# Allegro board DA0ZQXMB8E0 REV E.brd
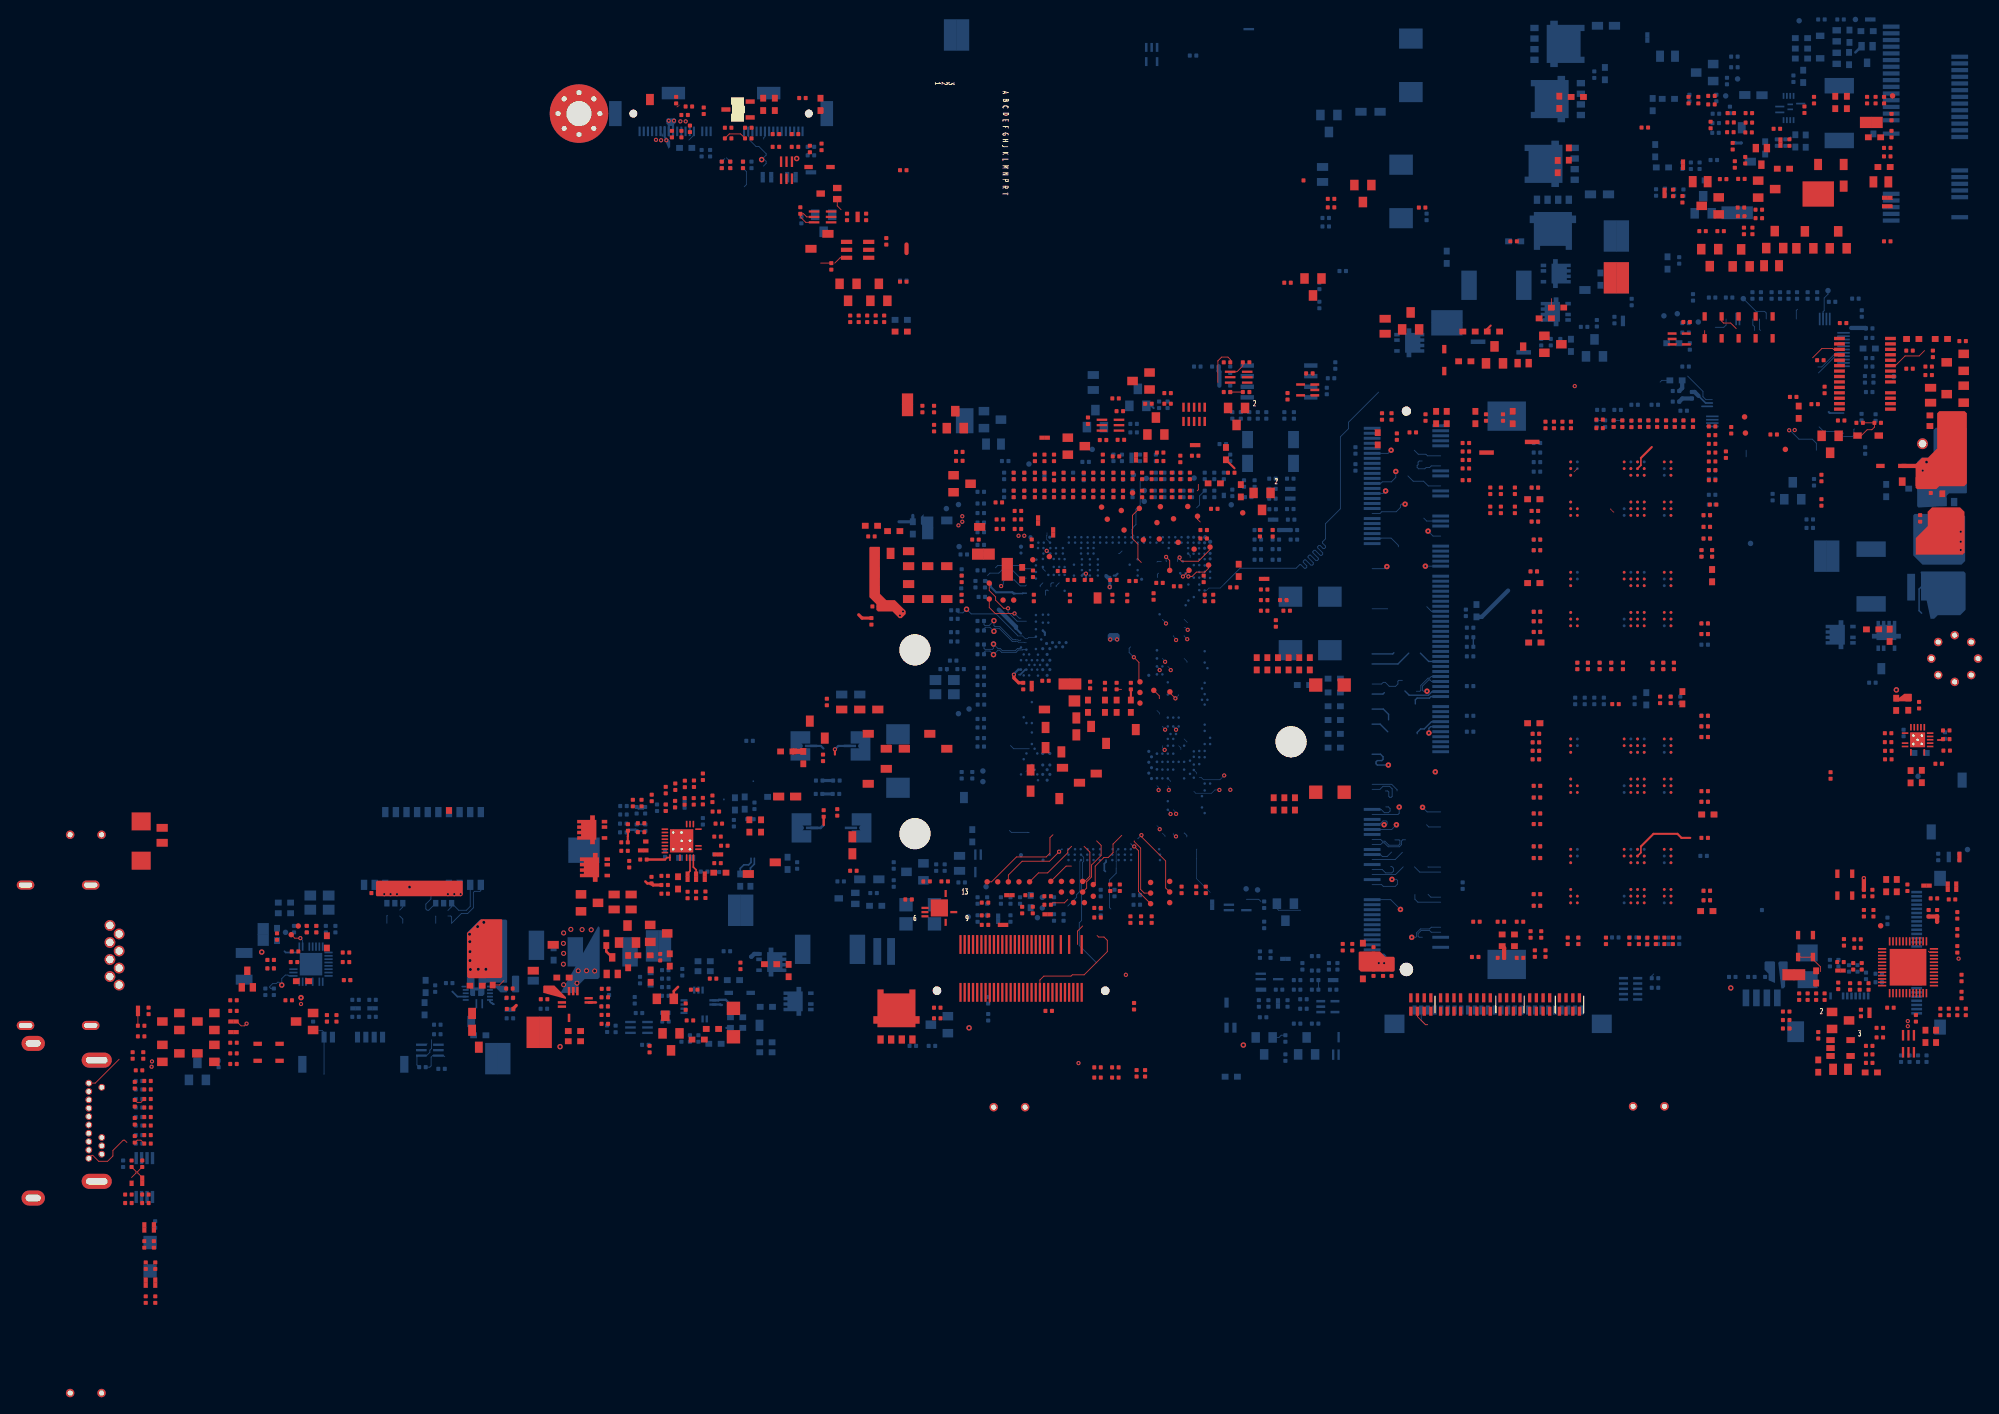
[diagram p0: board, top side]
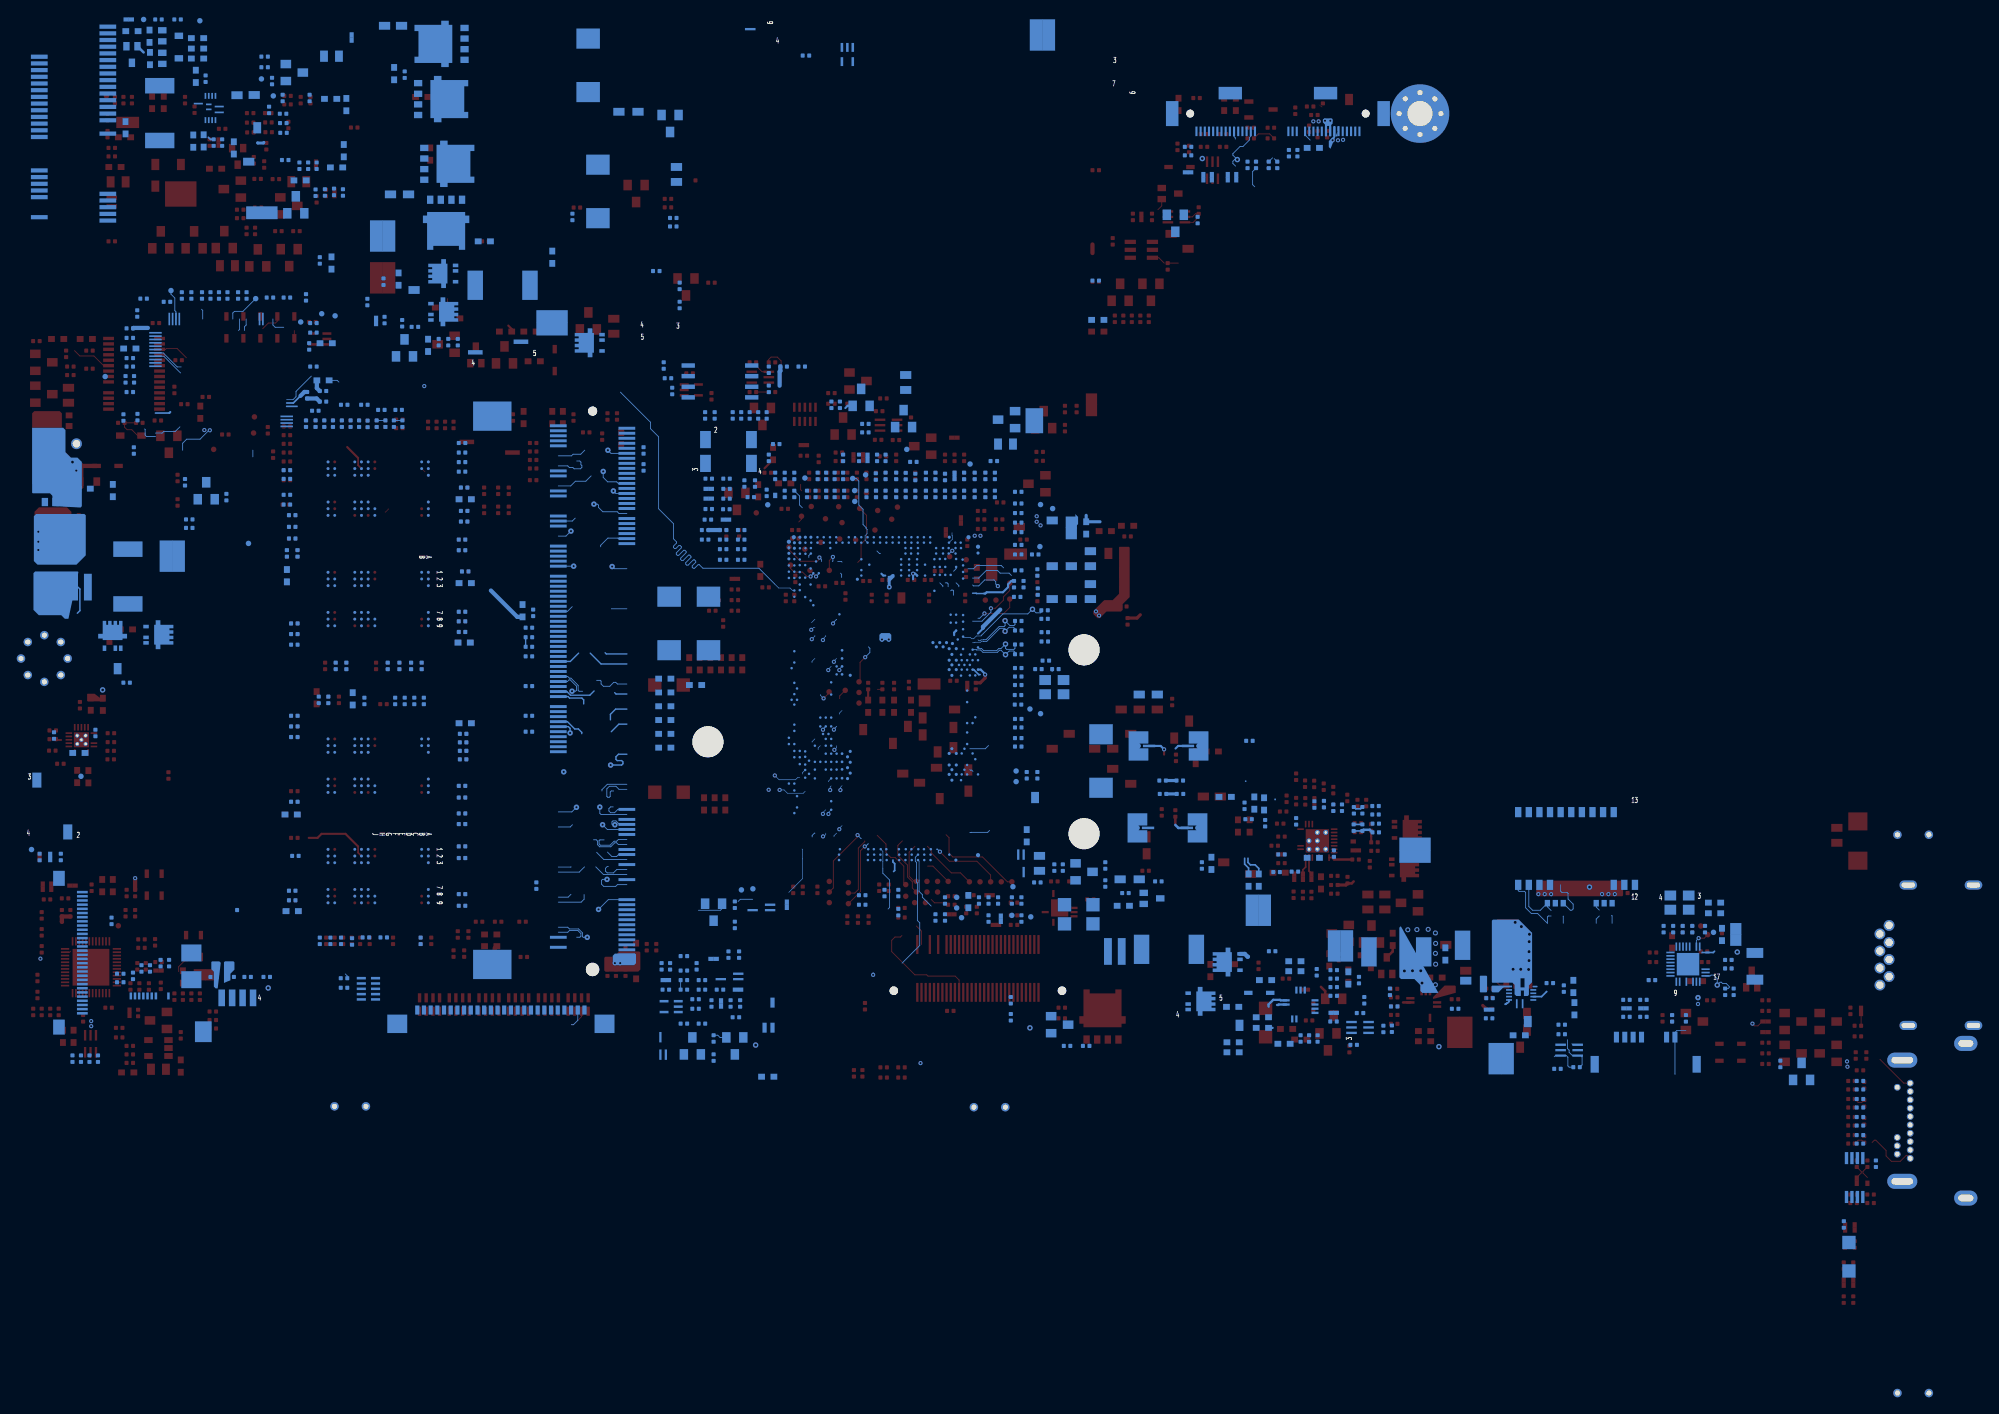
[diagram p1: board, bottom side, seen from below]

No outline. copper layers: TOP, SGND, IN1, IN2, SVCC, IN3, SGND1, BOTTOM. Coordinates in mm from the lowest, leftmost part position.

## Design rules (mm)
constraint set DEFAULT: min track width 0.102
net group W15-TB: nets SM_RCOMP_2

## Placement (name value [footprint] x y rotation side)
BT6  -  [ML1220-SMT]  214.22 66.2 295 bottom
C6  -  [CC0805]  75.61 152.88 0 top
C7  -  [CC0402]  77.84 152.81 90 top
C8  -  [CC0402#2]  219.19 152.81 90 top
C9  -  [CC0603#2]  88.26 152.3 270 top
C10  -  [CC0402]  79.37 152.05 0 top
C11  -  [CC0402]  79.49 149.38 270 top
C12  -  [CC0402]  81.14 151.54 90 top
C13  -  [CC0402]  78.86 151.03 0 top
C14  -  [CC0402#2]  105.02 151.03 0 top
C15  -  [CC0402]  223.26 150.78 90 top
C16  -  [CC0402]  86.48 149.51 0 top
C17  -  [CC0402]  77.33 148.74 270 top
C18  -  [CC0402]  78.48 148.74 90 top
C19  -  [CC0402]  223.26 148.74 270 top
C20  -  [CC0603#2]  221.23 148.36 0 top
C21  -  [CC0402]  86.48 148.24 0 top
C22  -  [CC0402#2]  139.18 147.09 90 top
C23  -  [CC0402]  222.75 147.09 0 top
C24  -  [CC0402#2]  144.39 146.71 180 top
C25  -  [CC0402#2]  146.42 146.71 180 top
C26  -  [CC0402#2]  147.95 146.71 270 top
C27  -  [CC0402#2]  105.02 146.46 180 top
C28  -  [CC0402]  222.75 146.08 0 top
C29  -  [CC0402#2]  135.12 145.57 90 top
C30  -  [CC0402#2]  105.02 145.44 180 top
C31  -  [CC0402]  83.3 145.06 270 top
C32  -  [CC0402]  84.32 145.06 270 top
C33  -  [CC0402]  85.84 145.06 90 top
C34  -  [CC0402#2]  133.6 145.06 0 top
C35  -  [CC0603]  137.15 145.06 0 top
C36  -  [CC0603]  139.82 145.01 180 top
C37  -  [CC0603]  142.49 145.06 0 top
C38  -  [CC0603]  145.28 145.06 0 top
C39  -  [CC0603]  148.07 145.06 180 top
C40  -  [CC0603#2]  222.37 144.81 0 top
C41  -  [CC0402#2]  105.02 143.41 180 top
C42  -  [CC0603]  137.41 143.03 270 top
C43  -  [CC0603]  138.93 143.03 270 top
C44  -  [CC0603]  140.4 143.03 90 top
C45  -  [CC0603]  142.1 143.03 90 top
C46  -  [CC0603]  144.39 143.03 270 top
C47  -  [CC0603]  145.91 143.03 90 top
C48  -  [CC0603]  135.12 142.47 0 top
C49  -  [CC0603]  150.61 142.52 270 top
C50  -  [CC0402#2]  105.02 142.39 180 top
C51  -  [CC0402#2]  148.71 142.14 180 top
C52  -  [CC0402#2]  130.67 141.96 0 top
C53  -  [CC0402#2]  105.02 141.38 180 top
C54  -  [CC0603]  135.12 141.12 0 top
C55  -  [CC0402#2]  145.79 140.49 90 top
C56  -  [CC0402#2]  148.07 140.49 270 top
C57  -  [CC0402#2]  149.22 140.49 270 top
C58  -  [CC0603]  137.41 140.36 270 top
C59  -  [CC0603]  138.93 140.36 270 top
C60  -  [CC0603]  140.4 140.36 270 top
C61  -  [CC0603]  142.1 140.36 270 top
C62  -  [CC0603]  144.39 140.36 270 top
C63  -  [CC0603]  104.77 140.11 0 top
C64  -  [CC0402#2]  135.37 139.85 0 top
C65  -  [CC0603]  150.61 139.73 270 top
C66  -  [CC0603]  152.14 139.73 270 top
C67  -  [CC0402#2]  148.58 138.84 0 top
C68  -  [CC0402#2]  105.02 138.71 180 top
C69  -  [CC0603]  135.12 138.58 180 top
C70  -  [CC0402#2]  145.79 138.46 90 top
C71  -  [CC0402#2]  105.02 137.7 180 top
C72  -  [CC0603]  137.41 137.7 90 top
C73  -  [CC0603]  138.93 137.7 90 top
C74  -  [CC0603]  140.4 137.7 270 top
C75  -  [CC0603]  142.1 137.7 270 top
C76  -  [CC0603]  144.39 137.7 90 top
C77  -  [CC0805#2]  148.3 137.19 0 top
C78  -  [CC0402#2]  105.02 136.68 0 top
C79  -  [CC0402#2]  145.79 136.43 90 top
C80  -  [CC0805]  93.97 135.92 90 top
C81  -  [CC0805]  96 135.92 270 top
C82  -  [CC0402]  102.99 135.92 270 top
C83  -  [CC0603]  134.99 135.92 0 top
C84  -  [CC0402]  222.75 135.92 180 top
C85  -  [CC0402#2]  139.56 134.77 270 top
C86  -  [CC0402#2]  140.58 134.77 90 top
C87  -  [CC0402#2]  105.02 134.52 0 top
C88  -  [CC0603]  137.02 134.52 90 top
C89  -  [CC0603]  138.29 134.52 270 top
C90  -  [CC0603]  141.85 134.52 270 top
C91  -  [CC0603]  143.37 134.52 90 top
C92  -  [CC0402#2]  144.77 134.52 90 top
C93  -  [RC0603#2]  134.99 134.39 0 top
C94  -  [CC0603]  147.06 134.39 270 top
C95  -  [CC0603]  149.09 134.39 270 top
C96  -  [CC0603]  150.49 134.39 270 top
C97  -  [CC0603]  130.29 132.74 90 top
C98  -  [CC0603]  131.69 131.85 90 top
C99  -  [CC0603]  134.23 131.85 90 top
C100  -  [CC0603]  135.88 131.85 270 top
C101  -  [CC0603]  139.95 131.85 90 top
C102  -  [CC0402#2]  132.96 130.71 90 top
C103  -  [CC0603]  128.52 130.58 90 top
C104  -  [CC0402#2]  130.04 130.33 270 top
C105  -  [CC0402#2]  138.29 129.82 90 top
C106  -  [CC0402#2]  128.52 128.04 90 top
C107  -  [CC0603]  129.91 127.79 90 top
C108  -  [CC0402#2]  105.03 127.79 0 top
C109  -  [CC0603]  104.77 126.52 0 top
C110  -  [CC0402]  217.47 126.14 0 top
C111  -  [CC0603#2]  104.77 125.12 0 top
C112  -  [CC0402#2]  140.83 125 270 top
C113  -  [CC0402#2]  141.85 125 270 top
C114  -  [CC0402#2]  143.12 125 270 top
C115  -  [CC0402#2]  144.14 125 270 top
C116  -  [CC0402#2]  145.41 125 270 top
C117  -  [CC0402#2]  146.42 125 270 top
C118  -  [CC0402#2]  147.44 125 270 top
C119  -  [CC0402#2]  148.58 125 270 top
C120  -  [CC0402#2]  105.02 123.85 0 top
C121  -  [CC0402#2]  105.02 122.84 180 top
C122  -  [CC0402]  225.42 122.84 180 top
C123  -  [CC0603#2]  229.23 124.23 180 top
C124  -  [CC0402]  214.75 121.69 0 top
C125  -  [CC0402]  220.11 110.89 270 bottom
C126  -  [CC0402]  215.26 118.14 90 top
C127  -  [CC0402]  150.99 117.38 270 top
C128  -  [CC0402]  162.3 114.96 270 top
C129  -  [CC0402]  163.44 114.96 270 top
C130  -  [CC0603#2]  212.16 115.47 90 top
C131  -  [CC0402]  167.5 114.84 270 top
C132  -  [CC0603#2]  168.77 114.84 90 top
C133  -  [CC0603#2]  170.04 114.84 90 top
C134  -  [CC0603#2]  173.47 114.84 90 top
C135  -  [CC0402]  174.74 114.84 270 top
C136  -  [CC0402]  176.78 114.84 270 top
C137  -  [CC0603#2]  177.92 114.84 90 top
C138  -  [CC0402]  188.33 114.58 0 top
C139  -  [CC0402]  219.45 114.2 0 top
C140  -  [CC0402]  181.86 113.95 270 top
C141  -  [CC0402]  182.87 113.95 270 top
C142  -  [CC0402]  183.89 113.95 270 top
C143  -  [CC0402]  184.9 113.95 270 top
C144  -  [CC0402]  204.08 113.31 90 top
C145  -  [CC0402]  209.16 112.8 180 top
C146  -  [CC0402]  164.08 112.55 90 top
C147  -  [CC0603#2]  161.79 112.3 90 top
C148  -  [CC0402]  203.45 110.39 90 top
C152  -  [CC0402]  214.88 107.6 270 top
C153  -  [CC0402]  172.33 107.34 0 top
C154  -  [CC0402]  201.79 107.34 180 top
C156  -  [CC0402]  180.59 106.45 0 top
C157  -  [CC0603#2]  145.41 106.07 270 top
C158  -  [CC0603#2]  180.46 105.06 180 top
C160  -  [CC0402]  116.45 104.68 180 top
C161  -  [CC0402]  214.88 104.68 270 top
C162  -  [CC0402]  201.92 104.42 180 top
C163  -  [CC0402]  142.23 103.91 0 top
C164  -  [CC0402]  180.59 103.66 0 top
C165  -  [CC0402]  201.16 103.15 180 top
C166  -  [CC0805]  114.16 102.64 90 top
C167  -  [CC0402]  180.59 102.39 0 top
C168  -  [CC0603#2]  101.21 101.88 180 top
C169  -  [CC0402]  201.16 101.75 180 top
C170  -  [CC0402]  147.69 100.99 90 top
C171  -  [CC0402]  149.22 100.99 90 top
C172  -  [CC0402]  101.21 100.61 0 top
C173  -  [CC0402]  201.16 100.36 180 top
C174  -  [CC0402]  113.66 100.23 0 top
C175  -  [CC0402]  180.84 100.23 0 top
C176  -  [CC0402]  120.39 99.85 90 top
C177  -  [CC0402]  180.84 98.96 0 top
C178  -  [CC0402]  201.79 98.58 270 top
C179  -  [CC0805]  107.94 97.94 90 top
C180  -  [CC0805]  110.23 97.94 90 top
C181  -  [CC0603#2]  145.15 96.55 270 top
C182  -  [CC0402]  123.89 96.47 180 top
C183  -  [CC0402]  180.46 96.42 0 top
C184  -  [CC0805]  102.61 96.29 0 top
C185  -  [CC0603#2]  119.24 96.17 90 top
C186  -  [CC0402]  120.54 96.14 270 top
C187  -  [CC0603#2]  201.79 95.91 270 top
C188  -  [CC0402]  112.01 95.53 90 top
C189  -  [CC0402]  140.96 95.53 90 top
C190  -  [CC0402]  125.09 95.4 180 top
C191  -  [CC0402]  127.12 95.4 0 top
C192  -  [CC0402]  130.17 95.4 180 top
C193  -  [CC0402]  132.45 95.28 180 top
C194  -  [CC0603#2]  180.46 95.02 180 top
C195  -  [CC0402]  144.52 94.52 0 top
C196  -  [CC0805]  102.61 94.01 0 top
C197  -  [CC0805]  107.94 94.01 90 top
C198  -  [CC0805]  110.23 94.01 90 top
C199  -  [CC0402]  112.01 93.25 270 top
C200  -  [CC0402]  120.64 93.25 270 top
C201  -  [CC0402]  124.96 93.25 90 top
C202  -  [CC0805]  127.37 93.25 180 top
C203  -  [CC0402]  130.04 93.25 90 top
C204  -  [CC0402]  131.82 93.25 270 top
C205  -  [CC0402]  150.49 92.99 0 top
C206  -  [CC0402]  101.72 92.23 0 top
C207  -  [CC0402]  180.84 91.59 0 top
C208  -  [CC0402]  101.21 90.45 90 top
C209  -  [CC0402]  180.84 90.45 0 top
C210  -  [CC0402]  149.6 90.2 270 top
C211  -  [CC0402]  200.91 90.2 180 top
C212  -  [CC0402]  180.84 89.18 0 top
C213  -  [CC0402]  200.91 88.93 180 top
C214  -  [CC0603#2]  180.59 87.91 180 top
C215  -  [CC0603#2]  147.31 85.37 90 top
C216  -  [CC0603#2]  148.58 85.37 270 top
C217  -  [CC0603#2]  149.85 85.37 270 top
C218  -  [CC0603#2]  151.12 85.37 90 top
C219  -  [CC0603#2]  152.39 85.37 270 top
C220  -  [CC0603#2]  153.66 85.37 90 top
C221  -  [CC0402]  185.67 85.12 90 top
C222  -  [CC0402]  186.94 85.12 90 top
C223  -  [CC0402]  188.33 85.12 90 top
C224  -  [CC0402]  189.73 85.12 90 top
C225  -  [CC0402]  191.13 85.12 90 top
C226  -  [CC0402]  194.68 85.12 90 top
C227  -  [CC0402]  195.95 85.12 90 top
C228  -  [CC0402]  197.22 85.12 90 top
C229  -  [CC0402]  127.37 82.83 90 top
C230  -  [CC0402]  129.15 82.7 270 top
C231  -  [CC0402]  130.55 82.7 270 top
C232  -  [CC0402]  132.25 82.7 270 top
C233  -  [CC0603#2]  198.24 81.31 90 top
C234  -  [CC0402]  196.84 81.05 270 top
C235  -  [CC0805]  97.65 80.8 90 top
C236  -  [CC0805]  99.81 80.8 90 top
C237  -  [CC0805]  101.97 80.8 90 top
C238  -  [CC0805]  121.91 80.8 90 top
C239  -  [CC0402]  190.24 80.55 180 top
C240  -  [CC0603#2]  127.12 80.29 270 top
C241  -  [CC0402]  200.91 79.15 180 top
C242  -  [CC0805]  124.83 78.89 180 top
C243  -  [CC0805]  94.73 78.51 0 top
C244  -  [CC0603#2]  180.46 78.26 180 top
C245  -  [CC0805]  128.39 77.88 0 top
C246  -  [CC0402]  200.91 77.88 180 top
C247  -  [CC0805]  121.15 77.75 180 top
C248  -  [CC0805]  131.94 77.5 180 top
C249  -  [CC0402]  180.71 76.99 0 top
C250  -  [CC0805]  124.83 76.86 180 top
C251  -  [CC0402]  200.91 76.61 180 top
C252  -  [CC0805]  94.73 76.48 180 top
C253  -  [CC0805]  100.83 76.1 270 top
C254  -  [CC0805]  102.99 76.1 90 top
C255  -  [CC0805]  105.15 76.1 90 top
C256  -  [CC0805]  108.2 76.1 270 top
C257  -  [CC0805]  110.23 76.1 90 top
C258  -  [CC0402]  180.71 75.97 0 top
C259  -  [CC0805]  128.39 75.85 180 top
C260  -  [CC0805]  121.15 75.34 180 top
C261  -  [CC0402]  180.71 74.96 0 top
C262  -  [CC0805]  124.83 74.83 0 top
C263  -  [CC0402]  180.71 73.94 0 top
C264  -  [CC0805]  128.11 73.13 90 top
C265  -  [CC0805]  121.15 72.67 0 top
C266  -  [CC0805]  124.07 72.04 270 top
C267  -  [CC0805]  126.1 72.04 90 top
C268  -  [CC0805]  100.83 71.91 90 top
C269  -  [CC0805]  102.99 71.91 270 top
C270  -  [CC0402]  180.84 70.77 0 top
C271  -  [CC0805]  121.15 70.13 0 top
C272  -  [CC0402]  200.91 70.13 180 top
C273  -  [CC0402]  180.84 69.37 0 top
C274  -  [CC0805]  124.58 69.24 0 top
C275  -  [CC0402]  200.91 68.86 180 top
C276  -  [CC0603#2]  149.34 68.61 90 top
C277  -  [CC0603#2]  150.61 68.61 90 top
C278  -  [CC0603#2]  151.88 68.61 270 top
C279  -  [CC0402]  180.84 67.46 0 top
C280  -  [CC0603#2]  201.29 67.34 0 top
C281  -  [CC0402]  180.84 66.19 180 top
C282  -  [CC0805]  98.04 64.67 180 top
C283  -  [CC1808]  13.83 64.16 90 top
C284  -  [CC0402]  180.84 63.53 0 top
C285  -  [CC0805]  98.04 62.64 180 top
C286  -  [CC0402]  180.84 62.13 0 top
C287  -  [CC0402]  109.97 59.34 0 top
C288  -  [CC0603#2]  222.62 58.83 90 top
C289  -  [CC0603#2]  223.89 58.83 90 top
C290  -  [CC0402]  225.16 58.57 270 top
C291  -  [CC0402]  201.16 58.22 180 top
C292  -  [CC0402]  41.77 57.94 180 top
C293  -  [CC0402]  180.84 57.81 0 top
C294  -  [CC0402]  228.34 57.3 180 top
C295  -  [CC0402]  230.5 57.18 0 top
C296  -  [CC0402]  201.16 57.08 180 top
C297  -  [CC0402]  180.84 56.42 0 top
C298  -  [CC0603#2]  201.16 55.78 0 top
C299  -  [CC0402]  219.96 55.53 270 top
C300  -  [CC0402]  221.1 55.53 270 top
C301  -  [CC0402]  227.7 55.53 270 top
C302  -  [CC0402]  228.72 55.53 270 top
C303  -  [CC0402]  231.13 55.27 90 top
C304  -  [CC0402]  176.52 54.51 180 top
C305  -  [CC0402]  33.65 53.62 270 top
C306  -  [CC0402]  34.79 53.62 270 top
C307  -  [CC0402]  231.13 53.24 270 top
C308  -  [CC0402]  181.35 52.99 90 top
C309  -  [CC0402]  30.09 52.73 90 top
C310  -  [CC0402]  184.52 52.22 90 top
C311  -  [CC0402]  185.79 52.22 90 top
C312  -  [CC0402]  189.09 52.22 90 top
C313  -  [CC0402]  191.89 52.22 90 top
C314  -  [CC0402]  193.03 52.22 90 top
C315  -  [CC0402]  194.05 52.22 90 top
C316  -  [CC0402]  195.06 52.22 90 top
C317  -  [CC0402]  196.08 52.22 90 top
C318  -  [CC0402]  197.1 52.22 90 top
C319  -  [CC0603#2]  36.06 52.1 270 top
C320  -  [CC0402]  219.19 52.4 180 top
C321  -  [CC0402]  158.74 51.46 270 top
C322  -  [CC0402]  217.57 52.05 270 top
C323  -  [CC0402]  231.13 51.21 270 top
C324  -  [CC0402]  32.25 50.95 0 top
C325  -  [CC0402]  38.35 50.83 180 top
C326  -  [CC0402]  181.86 50.7 270 top
C327  -  [CC0402]  176.52 50.19 180 top
C328  -  [CC0402]  32.12 49.68 180 top
C329  -  [CC0402]  38.35 49.68 180 top
C330  -  [CC0402]  218.68 49.18 270 top
C331  -  [CC0402]  219.69 49.18 270 top
C332  -  [CC0603#2]  160.01 48.41 90 top
C333  -  [CC0402]  162.42 48.41 270 top
C334  -  [CC0402]  163.44 48.41 90 top
C335  -  [CC0603#2]  214.24 47.91 270 top
C336  -  [CC0402]  38.47 47.53 180 top
C337  -  [CC0603#2]  33.14 47.4 180 top
C338  -  [CC0402]  218.3 46.76 270 top
C339  -  [CC0402]  220.51 46.76 90 top
C340  -  [CC0402]  231.64 45.75 90 top
C341  -  [CC0402]  212.21 45.54 90 top
C342  -  [CC0402]  213.22 45.54 90 top
C343  -  [CC0402]  214.24 45.54 90 top
C344  -  [CC0402]  215.26 45.54 90 top
C345  -  [CC0402]  210.66 43.77 180 top
C346  -  [CC0402]  226.18 42.95 90 top
C347  -  [CC0402]  229.1 43.72 90 top
C348  -  [CC0402]  230.12 43.72 90 top
C349  -  [CC0402]  232.15 43.72 90 top
C350  -  [CC0402]  36.06 42.95 270 top
C351  -  [CC0402]  37.2 42.95 270 top
C352  -  [CC0402]  214.49 40.92 270 top
C353  -  [CC0402]  13.83 40.79 180 top
C354  -  [CC0603#2]  227.32 40.79 270 top
C355  -  [CC0603#2]  228.59 40.79 270 top
C356  -  [CC0402]  14.09 38.51 270 top
C357  -  [CC0402]  220.59 37.62 180 top
C358  -  [CC0603#2]  214.49 37.24 270 top
C359  -  [CC0402]  13.58 36.73 180 top
C360  -  [CC0603#2]  220.84 36.48 0 top
C361  -  [CC0402]  14.6 35.46 0 top
C362  -  [CC0402]  14.6 34.44 0 top
C363  -  [CC0402]  14.6 33.3 0 top
C364  -  [CC0402]  14.6 32.29 0 top
C365  -  [CC0402]  14.6 31.14 0 top
C366  -  [CC0402]  14.6 30.13 0 top
C367  -  [CC0402]  14.6 28.98 0 top
C368  -  [CC0402]  14.6 27.97 0 top
C369  -  [CC0402]  12.69 25.55 90 top
C370  -  [CC0402]  13.96 25.55 90 top
C371  -  [CC0402]  12.31 21.87 0 top
C372  -  [CC0402]  14.34 21.87 180 top
C373  -  [CC0402]  14.38 13.36 270 top
C374  -  [CC0402]  15.52 13.36 270 top
C375  -  [CC0402#2]  134.99 160.68 0 bottom
C376  -  [CC0402]  204.46 156.75 0 bottom
C377  -  [CC0402#2]  134.48 155.86 0 bottom
C378  -  [CC0402#2]  157.98 154.84 90 bottom
C379  -  [CC0603]  104.77 154.33 0 bottom
C380  -  [CC0402#2]  142.23 153.95 180 bottom
C381  -  [CC0402#2]  144.26 153.95 0 bottom
C382  -  [CC0402#2]  105.02 153.06 0 bottom
C383  -  [CC0402#2]  159 153.06 0 bottom
C384  -  [CC0402#2]  105.02 152.05 180 bottom
C385  -  [CC0402#2]  105.02 151.03 0 bottom
C386  -  [CC0402#2]  105.02 150.01 0 bottom
C387  -  [CC0402#2]  105.02 149 0 bottom
C388  -  [CC0402#2]  105.02 146.97 0 bottom
C389  -  [CC0402#2]  157.22 146.84 270 bottom
C390  -  [CC0402#2]  158.49 146.84 270 bottom
C391  -  [CC0402]  83.3 145.06 270 bottom
C392  -  [CC0402]  84.32 145.06 270 bottom
C393  -  [CC0402]  85.84 145.06 270 bottom
C394  -  [CC0402]  86.86 145.06 270 bottom
C395  ev@330u_2.5v_3528  [CC3528#2]  160.65 144.05 90 bottom
C396  -  [CC0603]  104.77 143.66 0 bottom
C397  -  [CC0402#2]  105.02 142.39 180 bottom
C398  -  [CC0402]  155.57 137.7 0 bottom
C399  -  [CC0402#2]  105.02 135.54 180 bottom
C400  -  [CC0402#2]  105.02 134.52 180 bottom
C401  -  [CC0402#2]  105.02 133.5 180 bottom
C402  -  [CC0402#2]  155.31 132.36 0 bottom
C403  -  [CC0402#2]  105.03 132.36 180 bottom
C404  -  [CC0402]  208.91 129.44 270 bottom
C405  -  [CC0402]  213.22 129.44 270 bottom
C406  -  [CC0402#2]  105.02 128.93 0 bottom
C407  -  [CC0402]  216.15 128.68 0 bottom
C408  -  [CC0402]  190.24 131.09 270 bottom
C409  -  [CC0402]  219.7 127.28 90 bottom
C410  -  [CC0603#2]  104.77 126.52 0 bottom
C411  -  [CC0402]  188 126.11 270 bottom
C412  -  [CC0402]  220.59 125.5 180 bottom
C413  -  [CC0402#2]  105.03 125.12 180 bottom
C414  -  [CC0402#2]  105.02 123.85 0 bottom
C415  -  [CC0402]  199.13 123.34 90 bottom
C416  -  [CC0402#2]  158.33 122.94 0 bottom
C417  -  [CC0402#2]  160.37 122.94 0 bottom
C418  -  [CC0402#2]  105.02 122.84 180 bottom
C419  -  [CC0402]  220.59 121.95 180 bottom
C420  -  [CC0402]  142.36 120.93 180 bottom
C421  -  [CC0402]  220.59 120.93 180 bottom
C422  -  [CC0402]  221.1 119.41 90 bottom
C423  -  [CC0603#2]  197.48 119.28 0 bottom
C424  -  [CC0402]  199.38 117.5 270 bottom
C425  -  [CC0402]  192.52 116.36 0 bottom
C426  -  [CC0402]  194.94 116.36 180 bottom
C427  -  [CC0402]  188.43 115.75 0 bottom
C428  -  [CC0402]  190.49 115.75 180 bottom
C429  -  [CC0402]  198.39 115.65 0 bottom
C430  -  [CC0402]  144.39 115.09 270 bottom
C431  -  [CC0402]  219.68 114.89 90 bottom
C432  -  [CC0402]  180.84 111.79 0 bottom
C433  -  [CC0402]  180.84 110.64 0 bottom
C434  -  [CC0402]  180.84 109.5 0 bottom
C435  -  [CC0402]  180.84 108.36 0 bottom
C436  -  [CC0402]  213.99 107.09 270 bottom
C437  18p/50v_4  [CC0402]  145.79 106.94 90 bottom
C438  18p/50v_4  [CC0402]  147.06 106.94 90 bottom
C439  -  [CC0402]  180.59 106.45 0 bottom
C440  -  [CC0603#2]  180.46 105.06 180 bottom
C441  -  [CC0402]  201.79 104.42 0 bottom
C442  -  [CC0402]  180.59 103.66 0 bottom
C443  -  [CC0402]  201.16 103.15 180 bottom
C444  -  [CC0402]  180.59 102.39 0 bottom
C445  -  [CC0402]  201.16 101.75 180 bottom
C446  -  [CC0805]  110.23 101.63 270 bottom
C447  -  [CC0402]  151.76 101.37 180 bottom
C448  -  [CC0402]  149.6 100.23 0 bottom
C449  -  [CC0402]  180.84 100.23 0 bottom
C450  -  [CC0402]  147.44 99.09 0 bottom
C451  -  [CC0402]  180.84 98.96 0 bottom
C452  -  [CC0402]  200.52 98.58 270 bottom
C453  -  [CC0402]  201.79 98.58 270 bottom
C454  -  [CC0805]  107.94 97.94 90 bottom
C455  -  [CC0805]  110.23 97.94 90 bottom
C456  -  [CC0402]  180.46 96.42 0 bottom
C457  -  [CC0402]  112.01 96.29 90 bottom
C458  -  [CC0603#2]  201.79 95.91 270 bottom
C459  -  [CC0603#2]  180.46 95.02 180 bottom
C460  -  [CC0805]  107.94 94.01 90 bottom
C461  -  [CC0805]  110.23 94.01 90 bottom
C462  -  [CC0402]  111.95 94.01 270 bottom
C463  -  [CC0402]  111.14 91.77 180 bottom
C464  -  [CC0603#2]  173.6 91.72 270 bottom
C465  -  [CC0402]  180.84 91.59 0 bottom
C466  -  [CC0402]  172.33 91.47 270 bottom
C467  -  [CC0402]  111.14 90.75 180 bottom
C468  -  [CC0402]  114.29 90.5 180 bottom
C469  -  [CC0402]  180.84 90.45 0 bottom
C470  -  [CC7343]  151.35 90.2 90 bottom
C471  -  [CC7343]  156.06 90.2 90 bottom
C472  -  [CC0402]  200.91 90.2 180 bottom
C473  -  [CC0402]  172.84 89.69 180 bottom
C474  -  [CC0402]  114.29 89.35 180 bottom
C475  -  [CC0402]  180.84 89.18 0 bottom
C476  -  [CC0402]  111.12 89.16 180 bottom
C477  -  [CC0402]  200.91 88.93 180 bottom
C478  -  [CC0402]  111.12 88.04 0 bottom
C479  -  [CC0603#2]  180.59 87.91 180 bottom
C480  -  [CC0402]  114.29 87.68 180 bottom
C481  -  [CC0402]  114.29 86.51 180 bottom
C482  -  [CC0402]  172.84 86.26 180 bottom
C483  -  [CC0402]  185.67 85.12 90 bottom
C484  -  [CC0402]  186.94 85.12 90 bottom
C485  -  [CC0402]  188.33 85.12 90 bottom
C486  -  [CC0402]  189.73 85.12 90 bottom
C487  -  [CC0402]  194.68 85.12 90 bottom
C488  -  [CC0402]  195.95 85.12 90 bottom
C489  -  [CC0402]  109.85 84.74 0 bottom
C490  -  [CC0402]  111.88 84.74 180 bottom
C491  -  [CC0402]  114.29 83.85 0 bottom
C492  -  [CC0603#2]  156.58 83.59 180 bottom
C493  -  [CC0402]  114.29 82.83 0 bottom
C494  -  [CC0603#2]  152.9 82.83 0 bottom
C495  -  [CC0402]  172.84 82.7 180 bottom
C496  -  [CC0603#2]  156.58 81.94 180 bottom
C497  -  [CC0402]  114.32 81.63 0 bottom
C498  -  [CC0603#2]  193.92 81.18 90 bottom
C499  -  [CC0402]  196.84 81.05 270 bottom
C500  -  [CC0402]  197.98 81.05 270 bottom
C501  -  [CC0402]  185.41 80.93 270 bottom
C502  -  [CC0402]  186.55 80.93 270 bottom
C503  -  [CC0402]  187.7 80.93 270 bottom
C504  -  [CC0402]  188.84 80.93 270 bottom
C505  -  [CC0402]  192.52 80.93 270 bottom
C506  -  [CC0402]  114.32 80.49 0 bottom
C507  -  [CC0603#2]  156.58 80.29 180 bottom
C508  -  [CC0402]  172.84 79.15 180 bottom
C509  -  [CC0402]  200.91 79.15 180 bottom
C510  -  [CC0603#2]  156.58 78.64 180 bottom
C511  -  [CC0603#2]  180.46 78.26 180 bottom
C512  -  [CC0402]  200.91 77.88 180 bottom
C513  -  [CC0402]  172.84 77.24 180 bottom
C514  -  [CC0603#2]  156.58 76.99 180 bottom
C515  -  [CC0402]  180.71 76.99 0 bottom
C516  -  [CC0402]  200.91 76.61 180 bottom
C517  -  [CC0402]  180.71 75.97 0 bottom
C518  -  [CC0603#2]  156.58 75.34 180 bottom
C519  -  [CC0402]  180.71 74.96 0 bottom
C520  -  [CC0402]  180.71 73.94 0 bottom
C521  *330u_2.5v_3528  [CC3528#2]  108.83 73.94 270 bottom
C522  -  [CC0402]  180.84 70.77 0 bottom
C523  -  [CC0805]  113.17 69.37 0 bottom
C524  -  [CC0402]  180.84 69.37 0 bottom
C525  -  [CC0402]  180.84 67.46 180 bottom
C526  -  [CC0603#2]  201.29 67.34 0 bottom
C527  -  [CC0402]  180.84 66.19 0 bottom
C528  -  [CC0603#2]  113.28 64.8 90 bottom
C529  -  [CC0402]  180.84 63.53 0 bottom
C530  -  [CC0402]  200.78 62.38 180 bottom
C531  -  [CC0402]  228.85 62.26 270 bottom
C532  -  [CC0402]  231.39 62.26 270 bottom
C533  -  [CC0402]  180.84 62.13 0 bottom
C534  -  [CC0402]  103.88 61.24 270 bottom
C535  -  [CC0402]  108.96 60.99 270 bottom
C536  -  [CC0402]  112.01 59.21 0 bottom
C537  -  [CC0402]  171.95 58.83 270 bottom
C538  -  [CC0402]  201.16 58.22 180 bottom
C539  -  [CC0402]  180.84 57.81 0 bottom
C540  -  [CC0402]  201.16 57.08 180 bottom
C541  -  [CC0603#2]  30.98 56.8 0 bottom
C542  -  [CC0402]  180.84 56.42 0 bottom
C543  -  [CC0603#2]  201.16 55.78 0 bottom
C544  -  [CC0603#2]  30.98 55.53 0 bottom
C545  -  [CC0402]  148.2 54.13 90 bottom
C546  -  [CC0402]  222.77 54.61 270 bottom
C547  -  [CC0402]  32.12 53.62 270 bottom
C548  -  [CC0402]  33.65 53.62 270 bottom
C549  -  [CC0402]  34.79 53.62 270 bottom
C550  -  [CC0402]  37.08 53.62 270 bottom
C551  -  [CC0603#2]  30.09 52.99 90 bottom
C552  -  [CC0402]  190.21 52.63 180 bottom
C553  -  [CC0402]  192.35 52.63 180 bottom
C554  -  [CC0402]  185.79 52.22 90 bottom
C555  -  [CC0402]  195.32 52.22 90 bottom
C556  -  [CC0402]  196.59 52.22 90 bottom
C557  -  [CC0402]  197.86 52.22 90 bottom
C558  -  [CC0402]  148.96 50.57 90 bottom
C559  -  [CC0402]  215.89 49.56 270 bottom
C560  -  [CC0402]  216.91 49.56 270 bottom
C561  -  [CC0402]  152.77 49.18 270 bottom
C562  -  [CC3528]  213.22 49.18 270 bottom
C563  -  [CC0402]  218.18 48.92 270 bottom
C564  -  [CC0402]  219.19 48.92 270 bottom
C565  -  [CC0402]  206.49 47.91 180 bottom
C566  -  [CC0402]  204.21 47.91 0 bottom
C567  -  [CC0402]  208.53 47.91 0 bottom
C568  -  [CC0402]  210.56 47.91 180 bottom
C569  -  [CC0402]  194.96 47.75 0 bottom
C570  -  [CC0402]  38.47 47.53 180 bottom
C571  -  [CC0402]  154.3 47.53 180 bottom
C572  -  [CC0402]  194.96 46.61 0 bottom
C573  -  [CC0402]  149.98 46.38 180 bottom
C574  -  [CC0402]  28.69 46.13 90 bottom
C575  -  [CC0402]  29.71 46.13 90 bottom
C576  -  [CC0402]  49.01 46.51 270 bottom
C577  -  [CC0402]  39.49 43.13 180 bottom
C578  -  [CC0402]  41.52 43.13 0 bottom
C579  -  [CC0402]  152.14 42.32 0 bottom
C580  -  [CC0402]  11.68 25.55 270 bottom
C581  -  [CC0402]  15.51 18.29 270 bottom
C582  -  [CC1206]  14.9 14.43 90 bottom
C583  -  [CC0402#2]  220.97 81.99 0 bottom
C584  -  [CC0402#2]  225.39 116.05 180 top
C585  -  [CC0402#2]  223.71 105.97 90 bottom
C586  -  [CC0402#2]  190.11 156.08 270 bottom
C587  -  [CC0603]  225.59 117.22 180 top
C588  -  [CC0402#2]  158.26 150.06 90 bottom
C589  -  [CC0402#2]  168.65 134.01 90 bottom
C692  -  [CC0402]  215.97 72.01 90 top
C693  -  [CC0402#2]  216.12 68.2 180 top
C694  -  [CC0402#2]  211.32 142.17 180 top
C695  -  [CC0402#2]  211.32 141.12 180 top
C712  0.22u/25v_6  [CC0603]  45.33 41.18 180 bottom
C713  -  [CC0402#2]  45.58 45.24 0 top
C714  -  [CC0402#2]  45.2 42.32 180 bottom
C715  -  [CC0402#2]  220.72 134.01 0 top
C716  -  [CC0402#2]  217.62 131.19 270 top
C717  -  [CC0402#2]  216.6 131.19 270 top
CN6  -  [BSH-030-01-L-D-A-TR-60P-LDH]  119.12 48.92 0 top
CN7  -  [GS12401-1011-40P-R-NH-SMT]  83.22 151.2 0 bottom
CN8  -  [MINICARD-110021-52131-52P-RUV]  227.32 150.2 270 bottom
CN9  -  [50224-01001-001-10P-L]  214.24 141.4 180 bottom
CN10  -  [50271-0040N-V01-4P-L]  107.94 114.45 180 bottom
CN11  sub_conn  [50501-0300N-001-30P-L]  229.07 50.8 270 bottom
CN12  -  [RJ45-JM361C-HP34AA03-9H-8P]  0 50.5 90 bottom
CN13  -  [51553-01041-001-10P-L]  218.22 42.46 180 bottom
CN14  kb_conn  [50565-02601-001-26P-L]  176.19 42.29 180 bottom
CN15  -  [88266-040XX-XXX-4P-L]  207.72 41.35 180 bottom
CN16  -  [50501-00801-001-8P-L]  28.22 40.85 180 bottom
CN17  -  [50505-0080N-V01-8P-L]  39.22 37.45 180 bottom
CN18  59075-01942-001  [HDMI-59075-01942-001-19P]  0.92 30.7 90 bottom
CN19  -  [USB-YBA-USB-032-P01-9P-RUH-SMT]  1.52 11.2 90 bottom
CP6  *100p/50vx4  [8P4R]  166.95 44.6 180 top
CP7  *100p/50vx4  [8P4R]  170.5 44.6 180 top
CP8  *100p/50vx4  [8P4R]  174.06 44.6 180 top
CP9  *100p/50vx4  [8P4R]  177.61 44.6 180 top
CP10  *100p/50vx4  [8P4R]  181.17 44.6 180 top
CP11  *100p/50vx4  [8P4R]  184.73 44.6 180 top
D6  -  [RC0603]  89.65 152.3 90 top
D7  -  [RC0603]  95.11 152.3 270 top
D8  *1n4148ws  [DSM]  94.99 144.81 0 top
D9  -  [DSM]  200.91 125.63 270 top
D10  -  [DSM]  202.94 125.63 270 top
D11  -  [DSM]  204.97 125.63 270 top
D12  -  [DSM]  207 125.63 270 top
D13  -  [DSM]  209.03 125.63 270 top
D14  -  [DSMV]  220.46 112.68 180 top
D15  -  [DSM]  216.78 58.96 270 top
D16  -  [DSM]  218.56 58.96 270 top
D17  -  [DSM]  212.08 51.59 90 top
D18  -  [DSM]  213.86 51.59 90 top
D19  -  [DSM]  29.07 39.91 0 top
D20  -  [CC0402]  12.82 38.51 90 top
D21  -  [DSM]  29.07 37.87 0 top
D22  -  [CC0402]  12.31 20.86 0 top
D23  -  [CC0402]  14.34 20.86 180 top
D24  -  [CC0402]  14.22 15.9 90 top
D25  -  [CC0402]  15.36 15.9 90 top
D26  -  [CC0402]  14.38 9.3 90 top
D27  -  [CC0402]  15.52 9.3 90 top
D28  -  [CC0402]  204.46 158.02 0 bottom
D29  bat54c  [SOT23_213-3_3-2]  211.45 106.07 270 bottom
HOLE6  -  [H-C236D140P2]  158.62 162 180 bottom
HOLE7  -  [HG-C276D118P2]  66.22 151.2 0 top
HOLE8  -  [H-C236D140P2]  122.22 117.4 180 bottom
HOLE9  -  [H-C146D146N]  106.42 87.04 0 top
HOLE10  -  [HG-C315D146P2]  230.82 86 0 top
HOLE11  -  [H-C146D146N]  151.42 76.04 0 top
HOLE12  -  [HG-C315D118P2]  7.22 66.8 0 top
HOLE13  -  [H-C146D146N]  106.42 65.04 0 top
HOLE14  -  [HG-C315D158P2]  59.42 62.9 0 top
HOLE15  -  [HG-C315D118P2]  194.22 34.3 0 top
HOLE16  -  [HG-C315D118P2]  117.72 34.2 0 top
HOLE17  -  [HG-C315D118P2]  7.22 0 0 top
J6  *jump  [JOPEN25X30_S]  217.42 107.6 0 top
J7  *jump  [JOPEN25X30_S]  217.42 104.17 0 top
JDIM6  ddr3-dimm1_h=5.2_std  [DDR-C-2013289-204P]  165.22 82.2 90 bottom
JP6  -  [SHORT3720]  214.49 141.58 0 top
JP7  -  [SHORT3720]  190.34 131.55 90 top
JP8  -  [SHORT3720]  61.46 41.28 90 top
JP9  -  [SHORT3720]  111.4 160.61 270 bottom
JP10  -  [SHORT3720#2]  99.97 142.17 270 bottom
JP11  -  [SHORT3720#3]  204.79 140.08 180 bottom
JP12  -  [SHORT3720]  190.34 136.55 270 bottom
JP13  -  [SHORT3720]  170.07 126.16 180 bottom
JP14  -  [SHORT3720]  215.51 98.25 90 bottom
JP15  -  [SHORT3720]  66.82 63.07 0 bottom
JP16  -  [SHORT3720]  85.56 55.88 90 bottom
JP17  -  [SHORT3720]  75.73 51.61 90 bottom
JP18  -  [SHORT3720]  56.51 38.13 270 bottom
L6  ev@blm15px331sn1d  [RC0402#3]  152.52 143.21 180 top
L7  -  [RC0402#2]  152.52 141.53 0 top
L8  ev@blm15px331sn1d  [RC0402#2]  135.63 137.31 180 top
L9  -  [RC0805]  102.61 98.58 0 top
L10  -  [RC0805]  105.66 97.94 90 top
L11  -  [RC0805]  105.66 94.01 90 top
L12  -  [RC0805]  217.16 36.86 180 top
L15  blm15ag121sn1d/0.5a/120ohm_4  [RC0402]  218.94 129.06 180 bottom
L16  blm15ag121sn1d/0.5a/120ohm_4  [RC0402]  197.48 118.01 180 bottom
L17  blm15ag121sn1d/0.5a/120ohm_4  [RC0402]  197.48 116.74 180 bottom
L18  -  [RC0805]  105.66 97.94 90 bottom
L19  -  [RC0805]  105.66 94.01 90 bottom
L20  -  [L3_2X2_5-3_2]  26.15 49.18 270 bottom
L21  -  [RC0603]  47.74 44.1 90 bottom
L22  -  [RC0603]  47.87 46.76 270 bottom
L23  -  [RC0603#2]  49.01 44.1 90 bottom
MR6  ah9249ntr-g1  [SOT23_123-2_8-1_9]  85.25 151.69 0 top
NOREF  -  []  83.99 3.13 0 top
NOREF#2  -  []  88.26 159.67 0 top
NOREF#3  -  []  229.99 37.24 0 top
NOREF#4  -  []  143.22 53.09 0 top
NOREF#5  -  []  294.63 14.05 0 top
NOREF#6  -  []  22.75 67.03 0 top
NOREF#7  -  []  88.43 159.76 180 bottom
NOREF#8  -  []  22.75 67.03 180 bottom
NOREF#9  -  []  230.75 37.24 180 bottom
NOREF#10  -  []  155.03 65.66 180 bottom
PC6  -  [CC0603#2]  185.67 153.19 180 top
PC7  -  [CC0402]  213.99 152.81 270 top
PC8  -  [CC0603#2]  217.92 152.53 270 top
PC9  -  [CC0402]  193.74 149.53 0 top
PC10  -  [CC0603]  101.67 149.28 180 top
PC11  -  [CC0603#2]  184.65 146.36 270 top
PC12  *0.01u/25v_4  [CC0402]  205.76 145.62 90 top
PC13  -  [CC0805]  213.58 145.11 180 top
PC14  -  [CC0805]  218.43 145.11 0 top
PC15  -  [CC0402]  205.3 143.38 0 top
PC16  -  [CC0805]  218.43 142.52 0 top
PC17  -  [CC0402]  167.1 139.96 0 top
PC18  -  [CC0402]  207.38 139.7 180 top
PC19  -  [CC0402]  205.6 137.16 90 top
PC20  -  [CC0402]  178.05 135.92 0 top
PC21  -  [CC0603#2]  183.3 127.99 180 top
PC22  -  [CC0402]  100.7 126.65 270 top
PC23  -  [CC0603#2]  175.63 125.12 0 top
PC24  -  [CC0402]  136.64 116.49 180 top
PC25  -  [CC0603#2]  228.59 115.09 180 top
PC26  -  [CC0603#2]  228.59 113.82 180 top
PC27  -  [CC0402]  111.73 109.65 180 top
PC28  -  [CC0603#2]  229.35 106.45 90 top
PC29  -  [CC0603#2]  223.03 88.77 90 top
PC30  -  [CC0402]  95.88 80.8 270 top
PC31  -  [CC0603#2]  225.26 80.55 90 top
PC32  -  [CC0402]  226.56 80.42 90 top
PC33  -  [CC0402]  229.81 76.35 180 top
PC34  -  [CC0402]  229.86 74.98 180 top
PC35  1000p/50v_6  [CC0603#2]  91.08 74.88 0 top
PC36  -  [CC0402]  228.9 73.41 180 top
PC37  -  [CC0603#2]  226.89 71.88 90 top
PC38  -  [CC0603#2]  225.54 71.86 90 top
PC39  -  [CC0805]  90.11 70.39 90 top
PC40  -  [CC0805]  92.14 70.39 90 top
PC41  -  [CC0402]  74.92 69.32 270 top
PC42  -  [CC0603#2]  86.61 65.97 90 top
PC43  -  [CC0402]  71.67 64.01 0 top
PC44  -  [CC0402]  71.67 62.99 0 top
PC45  -  [CC0805]  89.7 62.51 90 top
PC46  -  [CC0402]  73.93 61.95 0 top
PC47  -  [CC0402]  82.8 61.52 180 top
PC48  -  [CC0805]  86.48 61.11 90 top
PC49  -  [CC0402]  99.05 60.61 0 top
PC50  -  [CC0402]  74.9 59.49 270 top
PC51  -  [CC0805]  63.14 50.85 270 top
PC52  -  [CC0402]  75.94 50.27 270 top
PC53  -  [CC0603#2]  89.15 49.43 0 top
PC54  -  [CC0402]  85.54 49.23 90 top
PC55  -  [CC0603#2]  74.79 48.01 90 top
PC56  -  [CC0603#2]  64.3 47.83 180 top
PC57  -  [CC0805]  60.75 47.75 270 top
PC58  -  [CC0402]  82.26 47.7 180 top
PC59  -  [CC0603#2]  53.92 46.86 0 top
PC60  -  [CC0402]  69.33 46.48 180 top
PC61  -  [CC0402]  132.63 44.4 90 top
PC62  -  [CC0402]  69.28 44.38 0 top
PC63  -  [CC0402]  57.98 44.07 0 top
PC64  -  [CC0805]  54.32 43.54 0 top
PC65  -  [CC0603#2]  82.19 41.68 0 top
PC66  -  [CC0805]  54.32 41.53 0 top
PC67  -  [CC0603#2]  65.68 41.43 0 top
PC68  -  [CC0603#2]  80.48 40.41 180 top
PC69  -  [CC0603#2]  65.68 40.21 180 top
PC70  -  [CC0805]  55.13 39.5 0 top
PC71  -  [CC0402#2]  198.87 39.4 0 top
PC72  -  [CC0402#2]  133.04 38.71 180 top
PC73  -  [CC0402]  130.39 37.09 180 top
PC74  -  [CC0402]  130.39 35.87 180 top
PC75  ev@4.7u/25v_8  [CC0805#2]  99.13 161.55 0 bottom
PC76  -  [CC0603#2]  220.34 161.06 0 bottom
PC77  ev@4.7u/25v_8  [CC0805]  188.08 160.81 270 bottom
PC78  ev@4.7u/25v_8  [CC0805]  190.11 160.81 270 bottom
PC79  ev@4.7u/25v_8  [CC0805#2]  102.25 160.78 90 bottom
PC80  ev@4.7u/25v_8  [CC0805#2]  104.28 160.78 90 bottom
PC81  ev@4.7u/25v_8  [CC0805#2]  106.34 160.78 90 bottom
PC82  -  [CC0603#2]  218.23 160.45 90 bottom
PC83  -  [CC0603#2]  212.49 160.22 0 bottom
PC84  -  [CC0402#2]  96.31 159.74 0 bottom
PC85  -  [CC0603]  108.8 159.06 270 bottom
PC86  -  [CC0603#2]  212.49 158.98 0 bottom
PC87  -  [CC0603#2]  212.49 157.79 0 bottom
PC88  -  [CC0603#2]  218.18 157.79 270 bottom
PC89  -  [CC0402#2]  97.4 157.35 180 bottom
PC90  -  [CC7343]  165.75 156.97 90 bottom
PC91  -  [CC0603#2]  188.97 155.98 270 bottom
PC92  -  [CC0402]  187.7 155.86 90 bottom
PC93  -  [CC0603#2]  212.69 155.65 90 bottom
PC94  -  [CC0402#2]  104.26 155.58 0 bottom
PC95  -  [CC0402]  203.57 155.09 270 bottom
PC96  -  [CC0603]  96.61 153.72 180 bottom
PC97  -  [CC0805]  205.71 152.53 270 bottom
PC98  -  [CC0805]  207.76 152.5 270 bottom
PC99  -  [CC0603#2]  194.68 152.27 90 bottom
PC100  sp@2700p/50v_4  [CC0402]  203.93 151.64 90 bottom
PC101  ev@10u/6.3v_8  [CC0805]  159.78 150.52 270 bottom
PC102  ev@10u/6.3v_8  [CC0805]  162.07 150.52 270 bottom
PC103  *0.01u/25v_4  [CC0402]  202.23 150.06 0 bottom
PC104  -  [CC0805]  206.24 149.51 0 bottom
PC105  -  [CC0603#2]  221.1 149.51 90 bottom
PC106  -  [ECAP6_3X6_1-7_2]  190.54 148.92 270 bottom
PC107  -  [CC0402]  202.2 148.9 0 bottom
PC108  -  [ECAP6_3X6_1-7_2]  172.56 148.64 180 bottom
PC109  -  [CC0603#2]  213 147.91 270 bottom
PC110  -  [CC0402]  209.54 147.73 270 bottom
PC111  -  [CC0402]  210.56 147.73 270 bottom
PC112  -  [CC0603#2]  208.14 147.09 270 bottom
PC113  -  [CC0603#2]  194.99 146.76 270 bottom
PC114  -  [CC0402]  202 145.65 180 bottom
PC115  -  [CC0402]  199.25 144.96 90 bottom
PC116  -  [CC0402]  200.3 144.96 90 bottom
PC117  -  [CC0805]  206.37 144.55 270 bottom
PC118  -  [CC0603]  96.56 142.95 180 bottom
PC119  -  [CC7343]  164.58 141.89 270 bottom
PC120  -  [CC0805#2]  96.36 141.12 180 bottom
PC121  ev@4.7u/25v_8  [CC0805]  187.24 140.64 270 bottom
PC122  ev@4.7u/25v_8  [CC0805]  189.4 140.64 270 bottom
PC123  -  [CC0402]  167.63 138.84 90 bottom
PC124  -  [CC0805#2]  98.72 137.11 270 bottom
PC125  -  [CC0805#2]  100.75 137.11 270 bottom
PC126  -  [CC0603#2]  178.17 135.92 180 bottom
PC127  -  [ECAP6_3X6_1-7_2]  203.27 134.9 0 bottom
PC128  -  [CC0603#2]  170.04 134.01 90 bottom
PC129  -  [CC0402]  197.86 133.63 270 bottom
PC130  -  [CC0603#2]  196.46 133.33 270 bottom
PC131  -  [ECAP6_3X6_1-7_2]  164.58 132.08 270 bottom
PC132  -  [CC0603#2]  188.43 131.4 270 bottom
PC133  -  [CC0805]  186.58 130.99 90 bottom
PC134  -  [CC0603#2]  184.9 123.47 270 bottom
PC135  -  [CC0402]  136.64 116.36 90 bottom
PC136  -  [CC0603#2]  226.05 106.33 180 bottom
PC137  -  [CC0603#2]  222.62 106.1 90 bottom
PC138  -  [ECAP6_3X6_1-7_2]  218.28 105.13 270 bottom
PC139  -  [CC0805]  221.15 84.79 180 bottom
PC140  2200p/50v_4  [CC0402]  220.97 83.11 0 bottom
PC141  -  [CC0805]  97.65 80.8 270 bottom
PC142  -  [CC0805]  99.81 80.8 270 bottom
PC143  -  [ECAP6_3X6_1-7_2]  219.09 77.12 180 bottom
PC144  -  [CC0402]  86.63 76.15 180 bottom
PC145  -  [CC0603#2]  226.69 74.7 0 bottom
PC146  -  [CC7343]  104.39 73.74 90 bottom
PC147  -  [CC0603#2]  89.53 69.45 0 bottom
PC148  0.22u/25v_6  [CC0603#2]  84.88 68.61 90 bottom
PC149  -  [CC0402]  78.86 68.53 270 bottom
PC150  2200p/50v_4  [CC0402]  87.21 68.38 270 bottom
PC151  -  [CC0402]  71.54 68.35 0 bottom
PC152  0.12u/10v_4  [CC0402]  74.13 67.85 90 bottom
PC153  -  [CC0402]  71.54 67.34 0 bottom
PC154  -  [CC0402]  86.73 66.78 180 bottom
PC155  -  [CC0402]  71.52 66.24 0 bottom
PC156  *0.15u/10v_4  [CC0402]  73.12 65.76 270 bottom
PC157  -  [CC0402]  71.52 65.2 0 bottom
PC158  0.33u/6.3v_4  [CC0402]  76.52 62.66 270 bottom
PC159  -  [CC0603#2]  78.99 62.16 180 bottom
PC160  -  [CC0603#2]  91.18 61.5 90 bottom
PC161  -  [CC0402]  92.32 61.24 90 bottom
PC162  -  [CC0805]  99.81 60.48 90 bottom
PC163  -  [CC0805]  102.1 60.48 90 bottom
PC164  -  [CC0402]  83.38 60.45 180 bottom
PC165  -  [CC0603#2]  85.51 59.49 90 bottom
PC166  -  [ECAP6_3X6_1-7_2]  68.34 57.96 180 bottom
PC167  -  [ECAP6_3X6_1-7_2]  77.69 57.56 0 bottom
PC168  -  [CC1206]  107.05 56.54 180 bottom
PC169  -  [CC0603#2]  101.72 56.42 180 bottom
PC170  -  [CC1206]  107.05 54.26 180 bottom
PC171  -  [CC0402]  83.91 50.98 0 bottom
PC172  -  [CC0603#2]  63.19 50.65 270 bottom
PC173  -  [CC0402]  76.55 48.72 180 bottom
PC174  -  [CC0603#2]  74.79 47.78 90 bottom
PC175  -  [CC0603#2]  57.9 47.63 0 bottom
PC176  -  [CC0402]  73.52 47.53 270 bottom
PC177  -  [CC0603#2]  84.7 47.53 180 bottom
PC178  0.1u/16v_4  [CC0402]  50.69 47.17 180 bottom
PC179  -  [CC0805]  60.75 46.56 270 bottom
PC180  -  [CC0402]  69.82 46.13 270 bottom
PC181  -  [CC0402]  57.9 45.37 0 bottom
PC182  -  [CC0603#2]  88.64 44.32 180 bottom
PC183  -  [CC0402]  62.02 44.1 180 bottom
PC184  -  [CC0603#2]  85.08 43.08 180 bottom
PC185  -  [CC0805]  54.22 42.57 0 bottom
PC186  -  [CC0402]  76.57 42.57 180 bottom
PC187  -  [CC0805]  88.71 42.11 0 bottom
PC188  -  [CC0603#2]  85.08 41.81 0 bottom
PC189  -  [CC0402]  69.59 41.71 270 bottom
PC190  -  [CC0603#2]  54.35 40.92 180 bottom
PC191  -  [CC0603#2]  88.59 40.08 0 bottom
PC192  -  [CC0603#2]  82.49 39.91 180 bottom
PC193  -  [CC0603#2]  88.59 38.89 180 bottom
PC194  -  [CC0603#2]  144.26 35.97 180 bottom
PC195  -  [CC0402#2]  223.26 66.96 180 top
PD6  -  [DSM]  169.75 121.69 90 top
PD7  -  [DSM]  223.23 109.04 0 top
PD8  1ps302  [UMT_213-3-1_3]  215.71 160.5 0 bottom
PD9  1ps302  [UMT_213-3-1_3]  220.34 158.27 90 bottom
PD10  1ps302  [UMT_213-3-1_3]  215.71 157.81 0 bottom
PD11  -  [D-DO-214AC]  227.02 108.43 180 bottom
PD12  -  [POWER-6_5-1_84-3P]  230.12 94.41 90 bottom
PD13  -  [DSM]  85.46 46 180 bottom
PJ6  power conn  [20288-04XX-4P-L]  228.22 111.7 180 bottom
PJ7  -  [50458-00801-V02-8P-L]  132.21 39.18 0 bottom
PL6  -  [CHOKE-ETQP4LR36AFM]  174.36 157.89 180 bottom
PL7  3.3uh_7x7x3  [CHOKE-PCMC063T-3R3MN-SMT#2]  217.01 151.26 90 bottom
PL8  ev@3.3uh_7x7x3  [CHOKE-PCMC063T-3R3MN-SMT]  100.32 149.18 270 bottom
PL9  -  [CHOKE-ETQP4LR36AFM]  173.7 140.72 180 bottom
PL10  -  [CHOKE-PCMC063T-3R3MN-SMT#2]  175.99 130.66 180 bottom
PL11  -  [CHOKE-PCMC063T-3R3MN-SMT#2]  220.82 95.81 90 bottom
PL12  -  [CHOKE-PCMC063T-R82MN-4P-SMT]  96.31 75.54 0 bottom
PL13  -  [CHOKE-PCMC063T-R82MN-4P-SMT]  96.44 65.74 0 bottom
PL14  3.3uh_7x7x3  [CHOKE-PCMC063T-3R3MN-SMT#2]  57.85 51.69 0 bottom
PL15  -  [CHOKE-PCMC063T-3R3MN-SMT#2]  96.26 51.21 180 bottom
PL16  -  [CHOKE-PCMC063T-3R3MN-SMT#2]  69.05 50.9 0 bottom
PQ6  -  [UMT_213-3-1_3]  207.69 146.08 90 top
PQ7  -  [SOT23_213-3_3-2]  208.32 142.17 180 top
PQ8  -  [SOT23_213-3_3-2]  201.57 140.16 0 top
PQ9  -  [SOT23_213-3_3-2]  209.29 136.12 270 top
PQ10  ao3404  [SOT23_213-3_3-2]  212.89 136.09 270 top
PQ11  ao3404  [SOT23_213-3_3-2]  216.88 136.09 270 top
PQ12  ev@2n7002k  [SOT23_213-3_3-2]  201.51 133.96 90 top
PQ13  ev@2n7002k  [SOT23_213-3_3-2]  205.27 133.94 270 top
PQ14  *pdtc143tt  [SOT23_213-3_3-2]  98.42 129.82 90 top
PQ15  -  [SOT23_213-3_3-2]  102.1 129.82 270 top
PQ16  -  [SOT23_213-3_3-2]  165.73 126.39 270 top
PQ17  -  [SOT23_213-3_3-2]  182.74 123.6 180 top
PQ18  -  [SOT23_213-3_3-2]  175.76 122.33 270 top
PQ19  -  [UMT_213-3-1_3]  179.19 122.33 270 top
PQ20  -  [SOT23_213-3_3-2]  133.47 119.2 0 top
PQ21  -  [SOT23_213-3_3-2]  230.88 117.63 0 top
PQ22  ev@2n7002k  [SOT23_213-3_3-2]  135.25 113.82 270 top
PQ23  *ao3404  [SOT23_213-3_3-2]  112.06 106.91 180 top
PQ24  -  [IMD]  225.54 105.97 90 top
PQ25  -  [WDFN5-3_05X3_05-65]  67.89 65.51 0 top
PQ26  -  [WDFN5-3_05X3_05-65]  68.22 61.01 0 top
PQ27  -  [SOT23_213-3_3-2]  67.48 56.77 180 top
PQ28  -  [SOT23_213-3_3-2]  75.76 53.11 180 top
PQ29  -  [SOT23_213-3_3-2]  72.03 53.04 270 top
PQ30  -  [UMT_213-3-1_3]  70.2 49.25 270 top
PQ31  -  [SOT23_213-3_3-2]  76.55 44.27 90 top
PQ32  -  [SO-8FL-5P-OA]  104.21 44.15 270 top
PQ33  -  [SOT23_213-3_3-2]  77.23 40.13 90 top
PQ34  -  [SO-8FL-5P-OA]  184.27 159.54 180 bottom
PQ35  -  [SOT23_213-3_3-2]  200.91 156.11 0 bottom
PQ36  -  [SO-8FL-5P-OA]  182.36 152.94 0 bottom
PQ37  -  [SO-8FL-5P-OA]  181.63 145.19 0 bottom
PQ38  -  [SOT23_213-3_3-2]  200.73 140.29 270 bottom
PQ39  -  [SO-8FL-5P-OA]  182.74 137.16 90 bottom
PQ40  -  [WDFN5-3_05X3_05-65]  183 132.06 180 bottom
PQ41  -  [WDFN5-3_05X3_05-65]  183.18 127.48 0 bottom
PQ42  -  [WDFN5-3_05X3_05-65]  165.47 123.78 180 bottom
PQ43  -  [SOT23_213-3_3-2]  187.72 123.17 270 bottom
PQ44  -  [SOT23_213-3_3-2]  133.09 117.25 270 bottom
PQ45  ev@2n7002k  [SOT23_213-3_3-2]  128.01 114.71 270 bottom
PQ46  -  [SOT23_213-3_3-2]  115.69 114.58 180 bottom
PQ47  -  [SO-8FL-5P-OA]  228.85 100.99 90 bottom
PQ48  -  [WDFN5-3_05X3_05-65]  217.26 88.85 0 bottom
PQ49  -  [WDFN5-3_05X3_05-65]  222.65 88.62 270 bottom
PQ50  -  [WDFN5-3_05X3_05-65]  89.15 49.68 180 bottom
PQ51  -  [WDFN5-3_05X3_05-65]  92.57 44.99 0 bottom
PQ52  -  [SOT23_213-3_3-2]  109.34 42.19 0 bottom
PQ53  -  [SC70-2_1-65-6P]  73.4 41.86 0 bottom
PQ64  -  [SOT23_213-3_3-2#2]  227.07 66.07 270 top
PQ65  -  [SOT23_213-3_3-2#2]  230.88 65.94 270 top
PQ66  -  [UMT_213-3-1_3#2]  226.31 62.51 0 top
PQ67  ao3404  [SOT23_213-3_3-2#2]  222.88 69.5 0 top
PR6  -  [RC0402]  201.72 153.32 180 top
PR7  *short 0_4  [SHORT0402]  212.26 153.32 0 top
PR8  ev@100k/f_4  [RC0402]  198.97 152.81 270 top
PR9  *0_4  [RC0402]  200.14 152.81 90 top
PR10  -  [RC0603]  183.51 152.55 270 top
PR11  *4.7_6  [RC0603]  216.53 152.53 90 top
PR12  -  [RC0402]  201.72 152.3 180 top
PR13  -  [RC0402]  212.84 151.67 270 top
PR14  *short 0_6  [SHORT0603]  211.55 151.31 270 top
PR15  -  [RC0402]  204.03 151.26 0 top
PR16  -  [RC0402]  206.19 151.26 180 top
PR17  -  [RC0402]  204 150.14 180 top
PR18  sp@0_4  [RC0402]  206.19 150.12 180 top
PR19  *4.7_6  [RC0603#2]  99.74 149.99 90 top
PR20  sp@20k/f_4  [RC0402]  201.62 149.84 270 top
PR21  -  [RC0402]  209.54 149.38 180 top
PR22  ev@10k/f_4  [RC0402]  203.98 148.97 180 top
PR23  -  [RC0402]  206.16 148.95 180 top
PR24  *short 0_4  [SHORT0402#2]  209.97 147.73 270 top
PR25  *0_4  [RC0402]  211.04 147.73 270 top
PR26  -  [RC0402]  204.26 147.3 270 top
PR27  -  [SHORT0603]  199.48 145.44 270 top
PR28  -  [SHORT0402#2]  198.31 145.09 270 top
PR29  -  [RC0402]  204.51 145.11 270 top
PR30  -  [RC0603]  183.33 144.86 270 top
PR31  -  [RC0603]  210.33 144.6 180 top
PR32  -  [RC0402]  203.12 143.36 0 top
PR33  22_8  [RC0805]  200.37 143.05 180 top
PR34  *short 0_4  [SHORT0402#2]  196.1 141.71 270 top
PR35  -  [RC0402]  197.12 141.71 270 top
PR36  -  [SHORT0402]  205.27 141.12 180 top
PR37  -  [RC0402]  198.24 140.95 270 top
PR38  1m_4  [RC0402]  205.25 139.96 180 top
PR39  1m_4  [RC0402]  205.27 138.91 180 top
PR40  1m_4  [RC0402]  207.38 138.69 180 top
PR41  ev@1m_4  [RC0402]  206.62 137.16 90 top
PR42  ev@1m_4  [RC0402]  200.65 137.14 0 top
PR43  ev@1m_4  [RC0402]  202.81 137.14 0 top
PR44  -  [RC0805]  208.91 133 0 top
PR45  *4.7_6  [RC0603]  181.83 126.7 180 top
PR46  *1m_4  [RC0402]  98.67 126.65 90 top
PR47  *1m_4  [RC0402]  99.69 126.65 270 top
PR48  *100k_4  [RC0402]  101.72 126.65 90 top
PR49  *0_4  [RC0402]  102.73 126.65 270 top
PR50  22_8  [RC0805]  162.68 125.76 270 top
PR51  -  [RC0603]  172.71 125.12 0 top
PR52  *short 0_6  [SHORT0603]  172.2 122.84 180 top
PR53  1m_6  [RC0603]  172.2 121.57 180 top
PR54  ev@1m_4  [RC0402]  136.64 117.76 180 top
PR55  ev@1m_4  [RC0402]  130.42 117.12 180 top
PR56  22_8  [RC0805]  227.93 117.5 270 top
PR57  ev@1m_4  [RC0402]  134.36 116.49 180 top
PR58  *1m_4  [RC0402]  111.73 110.72 180 top
PR59  220k_4  [RC0402]  227.96 106.2 90 top
PR60  -  [SHORT0805#2]  110.99 103.15 90 top
PR61  *short 0_4  [SHORT0402]  225.54 102.77 270 top
PR62  220k_4  [RC0402]  226.69 102.77 90 top
PR63  *4.7_6  [RC0603]  221 89.49 180 top
PR64  2/f_6  [RC0603]  223.82 80.52 270 top
PR65  *0_4  [RC0402#2]  227.58 80.42 90 top
PR66  -  [SHORT0402]  229.1 79.91 0 top
PR67  *short 0_4  [SHORT0402]  222.85 78.08 0 top
PR68  -  [RC0402]  229.81 77.4 0 top
PR69  *0_4  [RC0402]  222.85 77.07 180 top
PR70  *short 0_4  [SHORT0402]  221.33 76.07 90 top
PR71  82k/f_4  [RC0402]  222.85 76 180 top
PR72  200k/f_4  [RC0402]  222.88 74.96 180 top
PR73  -  [RC0603]  93.06 74.14 270 top
PR74  -  [RC0402]  95.42 74.12 90 top
PR75  *short 0_4  [SHORT0402]  96.84 74.12 270 top
PR76  -  [RC0402]  222.88 73.94 0 top
PR77  -  [RC0402]  81.04 71.86 90 top
PR78  -  [RC0402]  79.98 71.02 90 top
PR79  *90.9k/f_4  [RC0402]  78.88 70.99 90 top
PR80  -  [RC0402]  77.74 70.66 270 top
PR81  -  [RC0402]  76.6 70.26 270 top
PR82  *short 0_4  [SHORT0402]  83.23 69.24 270 top
PR83  -  [RC0402]  82.19 69.22 90 top
PR84  20k/f_4  [RC0402]  81.04 68.94 270 top
PR85  150k/f_4  [RC0402]  78.86 68.91 270 top
PR86  -  [RC0402]  79.95 68.91 270 top
PR87  2m/f_4  [RC0402]  72.66 68.71 270 top
PR88  -  [RC0402]  73.7 68.71 90 top
PR89  2m/f_4  [RC0402]  77.72 68.58 90 top
PR90  365k/f_4  [RC0402]  76.6 68.15 270 top
PR91  *100k/f_4  [RC0402]  82.59 67.69 0 top
PR92  *1.82k/f_4  [RC0402]  95.5 67.46 270 top
PR93  *0_4  [RC0402]  97.12 67.59 270 top
PR94  *0_4  [RC0402]  82.95 66.24 0 top
PR95  0_4  [RC0402]  73.65 66.3 0 top
PR96  -  [RC0603]  88 65.97 270 top
PR97  *10_4  [RC0402]  72.08 65.79 90 top
PR98  0_4  [RC0402]  73.65 65.23 0 top
PR99  *0_4  [RC0402]  82.8 64.7 180 top
PR100  *short 0_4  [SHORT0402#3]  73.91 64.11 180 top
PR101  150k/f_4  [RC0402]  83.61 63.6 0 top
PR102  *short 0_4  [SHORT0402#2]  73.91 63.04 180 top
PR103  *short 0_4  [SHORT0402#2]  82.85 62.56 180 top
PR104  *10_4  [RC0402]  72.23 61.39 90 top
PR105  -  [RC0603]  83.07 60.38 180 top
PR106  -  [RC0402]  76.47 60 0 top
PR107  *short 0_4  [SHORT0402#2]  79.21 59.89 90 top
PR108  *short 0_4  [SHORT0402#2]  80.23 59.89 90 top
PR109  *short 0_4  [SHORT0402#2]  81.27 59.89 90 top
PR110  20/f_6  [RC0603]  78.07 59.16 90 top
PR111  -  [RC0402]  76.47 58.9 180 top
PR112  -  [RC0402]  76.47 57.86 0 top
PR113  130/f_4  [RC0402]  81.35 57.74 270 top
PR114  56_4  [RC0402]  79.21 57.71 270 top
PR115  *75/f_4  [RC0402]  80.23 57.71 270 top
PR116  22_8  [RC0805]  70.43 56.87 90 top
PR117  22_8  [RC0805]  72.46 56.87 90 top
PR118  1m_6  [RC0603]  69.49 52.4 270 top
PR119  -  [RC0603]  74.01 50.5 180 top
PR120  1m_6  [RC0603]  77.08 49.94 270 top
PR121  1m_6  [RC0603]  72.1 49.73 90 top
PR122  *4.7_6  [RC0603]  91.3 48.67 270 top
PR123  *4.7_6  [RC0603]  55.9 47.68 90 top
PR124  *short 0_6  [SHORT0603]  62.42 47.12 90 top
PR125  *short 0_6  [SHORT0603]  84.83 46.76 270 top
PR126  82k/f_4  [RC0402]  57.9 46.51 0 top
PR127  -  [RC0402]  80 46.38 0 top
PR128  121k/f_4  [RC0402]  69.31 45.47 180 top
PR129  11k/f_4  [RC0402]  57.95 45.42 180 top
PR130  -  [RC0402]  62.04 45.24 0 top
PR131  -  [RC0402]  78.99 44.35 90 top
PR132  *short 0_6  [SHORT0603]  51.5 44.27 90 top
PR133  *short 0_4  [SHORT0402]  62.02 44.07 180 top
PR134  -  [RC0402]  69.31 43.36 0 top
PR135  sp@127k/f_4  [RC0402]  79.49 42.7 180 top
PR136  -  [RC1206]  84.7 42.45 90 top
PR137  113k/f_4  [RC0402]  69.31 42.29 180 top
PR138  *100k_4  [RC0402]  74.67 39.27 270 top
PR139  100_4  [RC0402]  128.26 37.09 0 top
PR140  100_4  [RC0402]  132.93 36.37 270 top
PR141  1m_4  [RC0402]  133.95 36.37 90 top
PR142  *short 0_4  [SHORT0402]  135.17 36.37 270 top
PR143  100_4  [RC0402]  128.26 35.87 0 top
PR144  -  [RC0402#2]  96.31 160.86 0 bottom
PR145  -  [SHORT0402]  99.05 159.44 270 bottom
PR146  -  [SHORT0603]  96.69 158.47 180 bottom
PR147  22_8  [RC0805]  196.46 158.07 180 bottom
PR148  ev@100k/f_4  [RC0402#2]  104.26 157.84 180 bottom
PR149  -  [SHORT0402]  106.62 157.88 180 bottom
PR150  -  [SHORT0402]  104.26 156.72 180 bottom
PR151  -  [RC0402#2]  95.8 156.67 270 bottom
PR152  -  [RC0402#2]  97.35 156.14 180 bottom
PR153  -  [RC0402]  211.52 155.37 90 bottom
PR154  -  [RC0603#2]  96.61 154.92 0 bottom
PR155  -  [SHORT0402]  197.35 154.26 0 bottom
PR156  *0_4  [RC0402]  199.08 153.06 90 bottom
PR157  -  [SHORT0402]  200.12 153.06 270 bottom
PR158  -  [SHORT0402]  201.16 153.06 270 bottom
PR159  -  [RC0402]  202.3 153.06 90 bottom
PR160  -  [RC0603]  196.56 152.96 180 bottom
PR161  sp@20k/f_4  [RC0402]  202.25 151.18 180 bottom
PR162  -  [SHORT0402]  203.98 149.46 270 bottom
PR163  1/f_6  [RC0603]  211.75 147.93 90 bottom
PR164  -  [SHORT0402]  204.16 147.75 0 bottom
PR165  -  [SHORT0402]  202 147.7 0 bottom
PR166  -  [SHORT0402]  202 146.66 0 bottom
PR167  -  [SHORT0402]  204.16 146.66 0 bottom
PR168  -  [SHORT0402]  204.16 145.65 180 bottom
PR169  -  [RC0402]  198.24 144.96 90 bottom
PR170  -  [RC0603]  195.85 144.76 180 bottom
PR171  -  [RC0603]  200.22 143.21 180 bottom
PR172  -  [RC0402]  195.09 141.76 270 bottom
PR173  82k/f_4  [RC0402]  196.16 141.84 90 bottom
PR174  *100k/f_4  [RC0402]  197.25 141.76 90 bottom
PR175  -  [RC0402]  198.37 141.73 90 bottom
PR176  *short 0_6  [SHORT0603]  194.96 133.4 270 bottom
PR177  200k/f_4  [RC0402]  181.35 123.85 90 bottom
PR178  200k/f_4  [RC0402]  182.49 123.85 270 bottom
PR179  1.58k/f_4  [RC0402]  183.63 123.85 270 bottom
PR180  -  [RC0402]  140.2 120.93 180 bottom
PR181  -  [RC0805]  127.75 119.03 90 bottom
PR182  -  [SHORT0402]  136.64 118.39 270 bottom
PR183  -  [RC0402]  135.63 116.36 270 bottom
PR184  -  [RC0805]  115.82 111.66 180 bottom
PR185  -  [RC3216]  226.43 94.54 90 bottom
PR186  *short 0_4  [SHORT0402]  225.82 91.04 90 bottom
PR187  *short 0_4  [SHORT0402]  226.86 91.04 90 bottom
PR188  *0_4  [RC0402]  224.71 77.09 90 bottom
PR189  -  [RC0402]  229.66 76.79 90 bottom
PR190  *short 0_6  [SHORT0603]  227.88 76.61 90 bottom
PR191  -  [RC0402]  94.96 71.4 180 bottom
PR192  10k/f_4_3435kntc  [RC0402]  97.02 71.4 0 bottom
PR193  -  [SHORT0805#2]  82.11 71.01 180 bottom
PR194  -  [RC0402]  94.94 69.8 180 bottom
PR195  *10k/f_4_3435kntc  [RC0402]  96.97 69.8 0 bottom
PR196  -  [SHORT0402]  83.56 68.73 90 bottom
PR197  2.2/f_6  [RC0603]  86.05 68.71 270 bottom
PR198  9.09k/f_4  [RC0402]  77.72 68.58 90 bottom
PR199  -  [RC0402]  75.56 68.15 270 bottom
PR200  *39.2k/f_4  [RC0402]  76.6 68.15 90 bottom
PR201  -  [RC0402]  73.12 67.85 90 bottom
